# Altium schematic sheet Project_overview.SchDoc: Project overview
size A4; Date: Not used; ApprovedBy: Not used; CheckedBy: Not used; Author: Not used; CompanyName: STMicroelectronics; DrawnBy: Not used; Engineer: Not used; Organization: Not used; Address1: Not used; Address2: Not used; Address3: Not used; Address4: Not used; DocumentNumber: 1; Revision: Not used; SheetNumber: 1; SheetTotal: 8
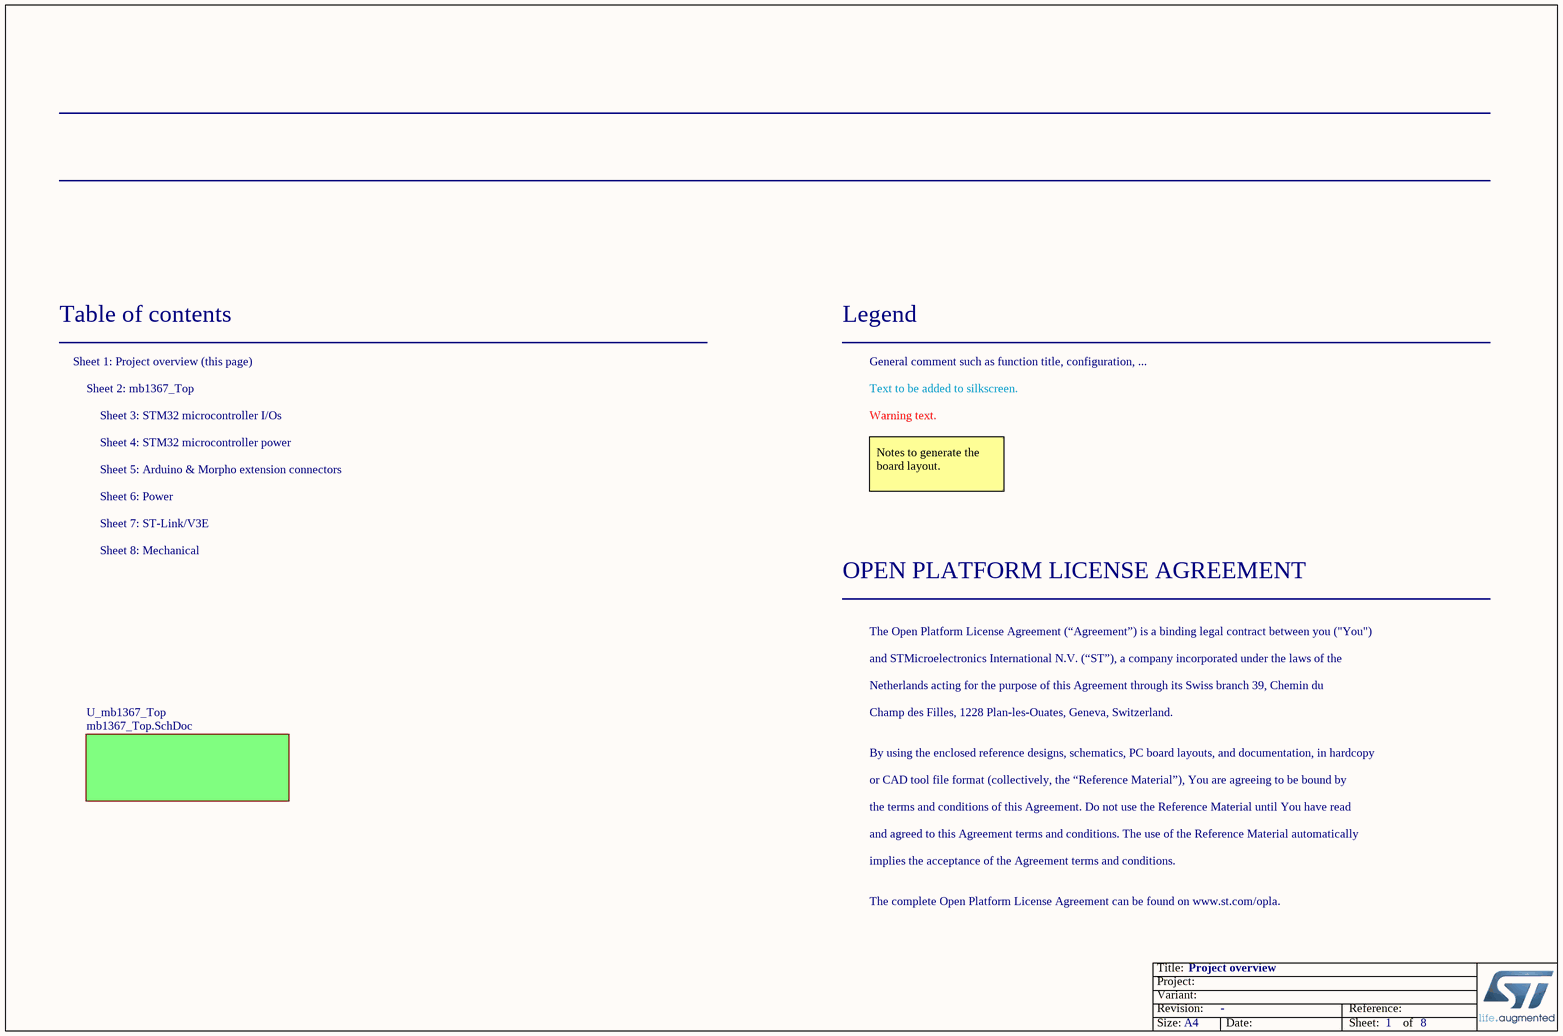
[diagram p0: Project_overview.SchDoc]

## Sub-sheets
U_mb1367_Top = mb1367_Top.SchDoc: no entries

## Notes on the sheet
- Table of contents
- Sheet 1: Project overview (this page)
- Legend
- General comment such as function title, configuration, ...
- Sheet 2: mb1367_Top
- Sheet 4: STM32 microcontroller power
- Sheet 3: STM32 microcontroller I/Os
- Text to be added to silkscreen.
- Warning text.
- Sheet 6: Power
- Sheet 5: Arduino & Morpho extension connectors
- Notes to generate the board layout.
- Sheet 7: ST-Link/V3E
- Sheet 8: Mechanical
- OPEN PLATFORM LICENSE AGREEMENT
- The Open Platform License Agreement (“Agreement”) is a binding legal contract between you ("You")
- and STMicroelectronics International N.V. (“ST”), a company incorporated under the laws of the
- Netherlands acting for the purpose of this Agreement through its Swiss branch 39, Chemin du
- Champ des Filles, 1228 Plan-les-Ouates, Geneva, Switzerland.
- By using the enclosed reference designs, schematics, PC board layouts, and documentation, in hardcopy
- or CAD tool file format (collectively, the “Reference Material”), You are agreeing to be bound by
- the terms and conditions of this Agreement. Do not use the Reference Material until You have read
- and agreed to this Agreement terms and conditions. The use of the Reference Material automatically
- implies the acceptance of the Agreement terms and conditions.
- The complete Open Platform License Agreement can be found on www.st.com/opla.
